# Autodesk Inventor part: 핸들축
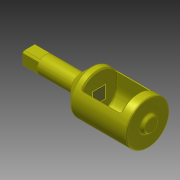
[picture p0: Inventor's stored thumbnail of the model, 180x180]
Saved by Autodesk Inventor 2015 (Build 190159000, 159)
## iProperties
Created: 2018-01
Part Number: 핸들축
Material: 강철, 연강
Document SubType Name: Modeling
Designer: mduedu
Density: 1 g/cm^3
Appearance: 노란색
Author: mduedu
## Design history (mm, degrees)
sketch "스케치1"
  geometry: L1 (0, 0)-(-109, 0); L2 (-46, -7.5)-(0, -7.5); L3 (0, -7.5)-(0, 0); L4 (-106, -19)-(-46, -19); L5 (-46, -19)-(-46, -7.5); L6 (-106, -7.5)-(-106, -19); L7 (-109, -5.768)-(-106, -7.5); L8 (-109, -5.768)-(-109, 0)
  constraints: 16 end point, 2 parallel, 1 horizontal, 1 vertical
  dimensions: "d8" = 15 diameter of L2 L1; "d43" = 46 distance between parallel lines of L3 L5; "d47" = 60 distance between parallel lines of L5 L6; "d63" = 3 distance between parallel lines of L6 L8; "d77" = 38 diameter of L4 L1; "d78" = 15 diameter of L6.start L1; "d79" = 30 deg angle of L1 L7
revolve "회전1" sketch "스케치1" stored, may be unused: angle "d9" = 90 deg
sketch "스케치4"
  geometry: L1 (-6, -6)-(-4.5, -6); L2 (6, -6)-(6, -4.5); L3 (6, 6)-(4.5, 6); L4 (-6, 6)-(-6, 4.5); L5 (-6, -6)-(6, 6); L6 (6, -6)-(-6, 6); L7 (-4.5, 6)-(-6, 6); L8 (-6, 4.5)-(-6, -4.5); L9 (-6, -4.5)-(-6, -6); L10 (-4.5, -6)-(4.5, -6); L11 (4.5, -6)-(6, -6); L12 (6, -4.5)-(6, 4.5); L13 (6, 4.5)-(6, 6); L14 (4.5, 6)-(-4.5, 6); C1 r 7.5 at (0, 0) reference; 2 further points
  constraints: 28 end point, 18 parallel, 9 perpendicular, 3 horizontal, 2 midpoint, 1 coincident, 11 other
  dimensions: "d20" = 12 distance of L4.start L3.start; "d21" = 12 distance of L3.start L2.start (= d20)
extrude "돌출2" cut sketch "스케치4" distance "d22" = 15; taper "d23" = 0 deg
chamfer "모따기2" distance "d24" = 1; stored, may be unused: second distance "d25" = 2, angle "d26" = 45 deg
sketch "스케치5"
  geometry: 2 further points
  constraints: 1 coincident
hole "구멍1" sketch "스케치5" at (5, 4.153) diameter "d27" = 2.459; stored, may be unused: countersink angle "d31" = 90 deg, drill point angle "d33" = 120 deg; dims "d28" = 6.9, "d29" = 4, "d30" = 2, "d32" = 8.4
node "작업 평면1"
sketch "스케치9"
  geometry: L1 (10, 4.153)-(10, 15.815); L2 (-20, 4.153)-(-20, 15.815); A1 r 15 centre (-5, 4.153) between (-20, 4.153) and (10, 4.153); A2 r 19 centre (-5, 4.153) between (10, 15.815) and (-20, 15.815) reference; 1 further point
  constraints: 4 end point, 4 point on circle, 2 tangent, 1 centre point, 1 coincident, 1 concentric, 1 parallel, 1 vertical
  dimensions: "d76" = 4 radial gap between concentric circles of A2 A1
extrude "돌출4" cut sketch "스케치9" distance "d73" = 34; taper "d74" = 0 deg
chamfer "모따기3" distance "d44" = 10; stored, may be unused: second distance "d45" = 2, angle "d46" = 45 deg
fillet "모깎기4" dims "d80" = 1
chamfer "모따기5" distance "d81" = 1; stored, may be unused: second distance "d82" = 2, angle "d83" = 45 deg
node "솔리드1"
other parameters: "d75" = -64
